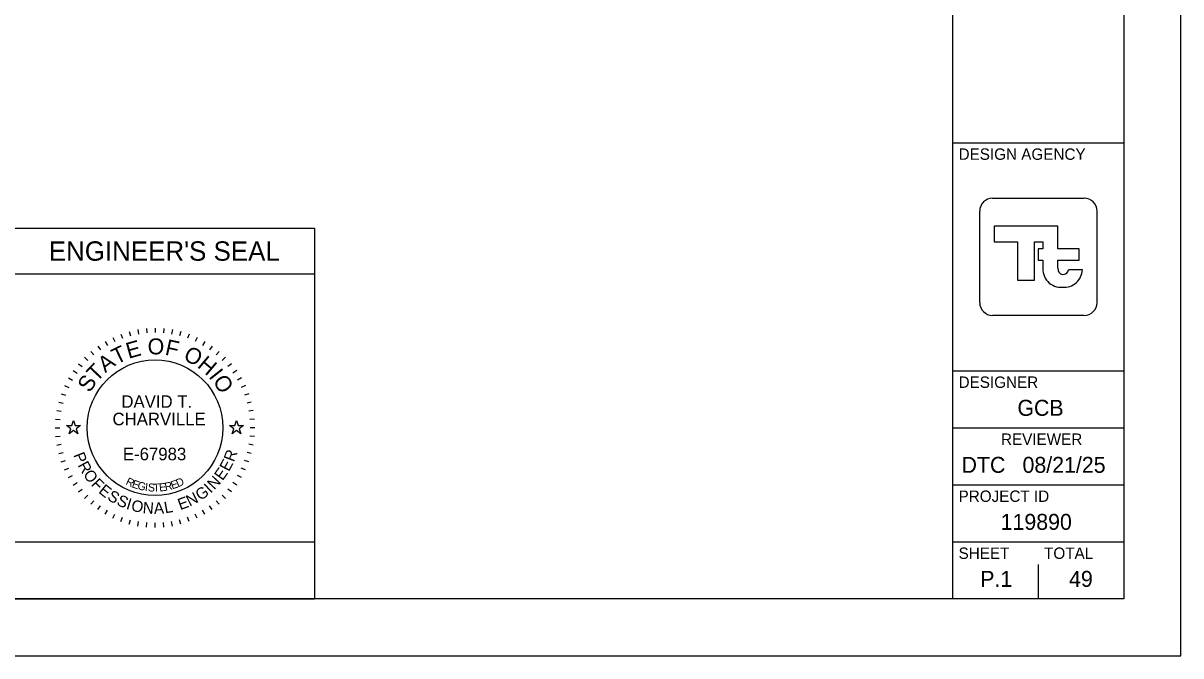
# Model space of a CAD drawing. Extents: x 0 to 42, y 0 to 22.
# Drawn here: x 23.84 to 34, y 0 to 5.55 of the extents above; entities that cross this region are included whole.
import ezdxf

# ---------------------------------------------------------------- set-up
doc = ezdxf.new("R2010")
doc.units = 0
for name, color, linetype in [('SH_Border', 7, 'Continuous'), ('SH_Cut_Line', 7, 'Continuous'), ('SH_Data', 7, 'Continuous'), ('SH_Seal', 7, 'Continuous')]:
    doc.layers.add(name, color=color, linetype=linetype)

msp = doc.modelspace()

# ---------------------------------------------------------------- linework, layer by layer
at = {"layer": 'SH_Border'}
for p, q in [((32, 0.5), (32, 21.5)), ((32, 4.5), (33.5, 4.5)), ((32, 2.5), (33.5, 2.5)), ((32, 2), (33.5, 2)), ((32, 1.5), (33.5, 1.5)), ((32, 1), (33.5, 1))]:
    msp.add_line(p, q, dxfattribs=at)
msp.add_lwpolyline([(1.5, 21.5), (33.5, 21.5), (33.5, 0.5), (1.5, 0.5)], close=True, dxfattribs=at)
at = {"layer": 'SH_Cut_Line'}
msp.add_lwpolyline([(0, 0), (34, 0), (34, 22), (0, 22)], close=True, dxfattribs=at)
at = {"layer": 'SH_Data'}
for p, q in [((23.6, 3.75), (26.4, 3.75)), ((26.4, 3.75), (26.4, 0.5)), ((32.75, 3.5), (32.75, 3.5)), ((32.791, 3.415), (32.791, 3.415)), ((33.136, 3.385), (33.015, 3.385)), ((23.6, 3.35), (26.4, 3.35)), ((32.75, 0.5), (32.75, 0.8)), ((32.375, 0.675), (32.375, 0.675)), ((23.6, 0.5), (26.4, 0.5))]:
    msp.add_line(p, q, dxfattribs=at)
for points in [[(32.348, 4.014), (33.152, 4.014)], [(32.236, 3.099), (32.236, 3.901)], [(33.264, 3.901), (33.264, 3.099)], [(32.922, 3.399), (32.922, 3.47), (33.107, 3.47), (33.107, 3.568), (32.922, 3.568), (32.922, 3.768), (32.361, 3.768), (32.361, 3.632), (32.566, 3.632), (32.566, 3.294), (32.715, 3.294), (32.715, 3.63), (32.79, 3.63), (32.79, 3.568), (32.748, 3.568), (32.748, 3.47), (32.79, 3.47), (32.79, 3.415), (32.791, 3.415)], [(33.152, 2.986), (32.348, 2.986)]]:
    msp.add_lwpolyline(points, dxfattribs=at)
msp.add_lwpolyline([(23.6, 0.5), (23.6, 1), (26.4, 1), (26.4, 0.5)], close=True, dxfattribs=at)
for centre, radius, start, end in [((32.348, 3.901), 0.113, 90, 180), ((33.152, 3.901), 0.113, 360, 90), ((32.949, 3.392), 0.16, 171.8856, 274.8323), ((32.968, 3.392), 0.0473, 171.8856, 350.9243), ((32.976, 3.392), 0.16, 265.1677, 357.3201), ((32.348, 3.099), 0.113, 180, 270), ((33.152, 3.099), 0.113, 270, 360)]:
    msp.add_arc(centre, radius, start, end, dxfattribs=at)
at = {"layer": 'SH_Seal'}
for p, q in [((24.774, 2.845), (24.784, 2.807)), ((24.848, 2.862), (24.855, 2.822)), ((24.924, 2.872), (24.927, 2.832)), ((25, 2.875), (25, 2.835)), ((25.076, 2.872), (25.073, 2.832)), ((25.152, 2.862), (25.145, 2.822)), ((25.226, 2.845), (25.216, 2.807)), ((24.563, 2.758), (24.583, 2.723)), ((24.63, 2.793), (24.647, 2.757)), ((24.701, 2.822), (24.714, 2.785)), ((25.299, 2.822), (25.286, 2.785)), ((25.37, 2.793), (25.353, 2.757)), ((25.437, 2.758), (25.417, 2.723)), ((24.438, 2.67), (24.463, 2.64)), ((24.498, 2.717), (24.521, 2.684)), ((25.502, 2.717), (25.479, 2.684)), ((25.562, 2.67), (25.537, 2.64)), ((24.33, 2.562), (24.36, 2.537)), ((24.381, 2.619), (24.41, 2.59)), ((25.619, 2.619), (25.59, 2.59)), ((25.67, 2.562), (25.64, 2.537)), ((24.283, 2.502), (24.316, 2.479)), ((25.717, 2.502), (25.684, 2.479)), ((24.207, 2.37), (24.243, 2.353)), ((24.242, 2.438), (24.277, 2.418)), ((25.758, 2.438), (25.723, 2.418)), ((25.793, 2.37), (25.757, 2.353)), ((24.178, 2.299), (24.215, 2.286)), ((25.822, 2.299), (25.785, 2.286)), ((24.138, 2.152), (24.178, 2.145)), ((24.155, 2.226), (24.193, 2.216)), ((25.845, 2.226), (25.807, 2.216)), ((25.862, 2.152), (25.822, 2.145)), ((24.128, 2.076), (24.168, 2.073)), ((25.872, 2.076), (25.832, 2.073)), ((24.125, 2), (24.165, 2)), ((25.875, 2), (25.835, 2)), ((24.128, 1.924), (24.168, 1.927)), ((24.138, 1.848), (24.178, 1.855)), ((25.862, 1.848), (25.822, 1.855)), ((25.872, 1.924), (25.832, 1.927)), ((24.155, 1.774), (24.193, 1.784)), ((25.845, 1.774), (25.807, 1.784)), ((24.178, 1.701), (24.215, 1.714)), ((24.207, 1.63), (24.243, 1.647)), ((25.793, 1.63), (25.757, 1.647)), ((25.822, 1.701), (25.785, 1.714)), ((24.242, 1.563), (24.277, 1.583)), ((25.758, 1.563), (25.723, 1.583)), ((24.283, 1.498), (24.316, 1.521)), ((24.33, 1.438), (24.36, 1.463)), ((25.67, 1.438), (25.64, 1.463)), ((25.717, 1.498), (25.684, 1.521)), ((24.381, 1.381), (24.41, 1.41)), ((24.438, 1.33), (24.463, 1.36)), ((25.562, 1.33), (25.537, 1.36)), ((25.619, 1.381), (25.59, 1.41)), ((24.498, 1.283), (24.521, 1.316)), ((24.563, 1.242), (24.583, 1.277)), ((24.63, 1.207), (24.647, 1.243)), ((25.37, 1.207), (25.353, 1.243)), ((25.437, 1.242), (25.417, 1.277)), ((25.502, 1.283), (25.479, 1.316)), ((24.701, 1.178), (24.714, 1.215)), ((24.774, 1.155), (24.784, 1.193)), ((24.848, 1.138), (24.855, 1.178)), ((24.924, 1.128), (24.927, 1.168)), ((25, 1.125), (25, 1.165)), ((25.076, 1.128), (25.073, 1.168)), ((25.152, 1.138), (25.145, 1.178)), ((25.226, 1.155), (25.216, 1.193)), ((25.299, 1.178), (25.286, 1.215))]:
    msp.add_line(p, q, dxfattribs=at)
for points in [[(24.224, 2.02), (24.271, 2.02), (24.285, 2.065), (24.299, 2.02), (24.346, 2.02), (24.308, 1.992), (24.323, 1.948), (24.285, 1.975), (24.247, 1.948), (24.262, 1.992)], [(25.654, 2.02), (25.701, 2.02), (25.715, 2.065), (25.729, 2.02), (25.776, 2.02), (25.738, 1.992), (25.753, 1.948), (25.715, 1.975), (25.677, 1.948), (25.692, 1.992)]]:
    msp.add_lwpolyline(points, close=True, dxfattribs=at)
msp.add_circle((25, 2), 0.595, dxfattribs=at)

# ---------------------------------------------------------------- texts
at = {"layer": 'SH_Data'}
for s, height, p in [('DESIGN AGENCY', 0.1, (32.05, 4.35)), ("ENGINEER'S SEAL", 0.17, (24.068, 3.465)), ('DESIGNER', 0.1, (32.05, 2.35)), ('GCB', 0.14, (32.566, 2.105)), ('REVIEWER', 0.1, (32.422, 1.85)), ('DTC', 0.14, (32.076, 1.605)), ('08/21/25', 0.14, (32.611, 1.605)), ('PROJECT ID', 0.1, (32.05, 1.35)), ('119890', 0.14, (32.419, 1.105)), ('SHEET', 0.1, (32.05, 0.85)), ('TOTAL', 0.1, (32.8, 0.85)), ('P.1', 0.14, (32.24, 0.605)), ('49', 0.14, (33.019, 0.605))]:
    msp.add_text(s, height=height, dxfattribs=at).set_placement(p)
at = {"layer": 'SH_Seal'}
for s, height, rotation, p in [('E', 0.14, 15.7571, (24.768, 2.604)), ('O', 0.14, 359.7812, (24.935, 2.644)), ('F', 0.14, 347.4362, (25.081, 2.642)), ('T', 0.14, 25.7167, (24.662, 2.552)), ('O', 0.14, 332.2586, (25.24, 2.602)), ('T', 0.14, 46.4344, (24.488, 2.396)), ('A', 0.14, 36.4747, (24.563, 2.478)), ('H', 0.14, 319.9136, (25.363, 2.536)), ('S', 0.14, 57.1924, (24.428, 2.301)), ('I', 0.14, 308.367, (25.466, 2.448)), ('O', 0.14, 303.1491, (25.502, 2.409)), ('P', 0.1, 291.494, (24.282, 1.762)), ('E', 0.1, 61.9951, (25.648, 1.61)), ('R', 0.1, 69.2322, (25.692, 1.695)), ('R', 0.1, 298.7311, (24.319, 1.672)), ('O', 0.1, 306.4666, (24.365, 1.588)), ('E', 0.1, 54.758, (25.593, 1.531)), ('F', 0.1, 314.7068, (24.434, 1.498)), ('R', 0.07, 334.487, (24.737, 1.505)), ('E', 0.07, 341.04, (24.791, 1.48)), ('G', 0.07, 347.4752, (24.841, 1.462)), ('R', 0.07, 11.9184, (25.092, 1.447)), ('E', 0.07, 17.6836, (25.15, 1.46)), ('D', 0.07, 23.3052, (25.201, 1.477)), ('N', 0.1, 47.0224, (25.52, 1.451)), ('E', 0.1, 321.4393, (24.498, 1.435)), ('S', 0.1, 328.6764, (24.574, 1.375)), ('I', 0.07, 353.7858, (24.909, 1.447)), ('S', 0.07, 356.8926, (24.936, 1.443)), ('T', 0.07, 3.0061, (24.986, 1.439)), ('E', 0.07, 6.0117, (25.039, 1.441)), ('N', 0.1, 27.3113, (25.304, 1.308)), ('G', 0.1, 35.0469, (25.398, 1.357)), ('I', 0.1, 43.287, (25.487, 1.421)), ('S', 0.1, 335.9134, (24.656, 1.327)), ('I', 0.1, 343.1505, (24.741, 1.29)), ('O', 0.1, 346.8859, (24.784, 1.275)), ('N', 0.1, 355.1261, (24.889, 1.252)), ('A', 0.1, 2.8617, (24.992, 1.244)), ('L', 0.1, 10.0987, (25.089, 1.249)), ('E', 0.1, 20.0742, (25.221, 1.277))]:
    msp.add_text(s, height=height, rotation=rotation, dxfattribs=at).set_placement(p)
for s, p in [('DAVID T.', (24.705, 2.175)), ('CHARVILLE', (24.627, 2.022)), ('E-67983', (24.718, 1.715))]:
    msp.add_text(s, height=0.11, dxfattribs=at).set_placement(p)

doc.saveas('drawing.dxf')
